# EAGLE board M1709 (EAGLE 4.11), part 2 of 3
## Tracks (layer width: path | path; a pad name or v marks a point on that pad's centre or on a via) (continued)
GND  (via drill 0.61) (continued)
  Top 0.381: U$2.AT2 212.72,13.97 212.72,24.77 BUS18.1 | U$2.AN2 225.43,13.97 225.43,24.77 BUS20.1 | U$2.AF1 244.47,13.97 244.47,24.77 BUS22.1 | U$2.AC1 254,13.97 v254,15.24 254,21.59 BUS23.1 | C4.2 157.48,80.65 157.48,75.57 159.38,73.66 v159.38,64.77 159.38,63.5 161.93,60.96 161.93,56.52 E3.1 | BUS7.1 224.79,32.39 224.16,33.02 224.16,41.91 C39.- | v90.17,66.04 90.17,79.38 88.9,80.65 R8.1 | 36.2,51.44 37.47,52.71 v37.47,59.69 37.47,61.6 | 37.47,61.6 36.2,62.87 E13.8 | 36.2,70.49 37.47,69.22 37.47,61.6 | BUS89.1 21.59,31.12 21.59,26.04 BUS97.1 22.23,24.77 v22.23,15.24 22.23,13.97 U$2.DN2 | U$2.DT2 9.53,13.97 9.53,24.77 BUS96.1 | E14.8 8.89,66.04 v5.71,62.87 3.81,60.96 3.81,37.47 8.89,32.39 BUS85.1 | U$2.CC1 120.65,13.97 v120.65,15.24 120.65,21.59 BUS81.1 | U$2.BT2 142.88,13.97 142.88,24.77 BUS41.1 | U$2.BN2 155.57,13.97 155.57,24.77 BUS42.1 | U$2.BF1 174.62,13.97 174.62,24.77 BUS47.1 | U$2.BC1 184.15,13.97 v184.15,15.24 184.15,21.59 BUS50.1 | C12.2 48.26,40.01 48.26,35.56 50.8,33.02 50.8,29.21 BUS95.1 | U$2.DF1 41.27,13.97 41.27,24.77 BUS99.1 40.64,26.04 40.64,31.12 BUS94.1 | U$2.DC1 50.8,13.97 50.8,21.59 BUS102.1 | U$2.CT2 79.38,13.97 79.38,24.77 BUS68.1 | U$2.CF1 111.12,13.97 v111.12,15.24 111.12,24.77 BUS78.1 | U$2.CN2 92.08,13.97 v92.08,15.24 92.08,24.77 BUS72.1 | E7.7 111.12,40.01 111.12,32.39 BUS64.1 | C3.2 157.48,55.25 155.57,53.34 155.57,32.39 BUS31.1 | E12.5 34.92,48.9 34.92,50.17 E12.4
  Bottom 0.381: C2.2 200.03,66.04 198.75,64.77 190.5,64.77 189.23,66.04 E2.7 186.69,66.04 185.42,64.77 v159.38,64.77 147.96,64.77 | C8.2 107.31,66.04 110.49,66.04 E8.7 113.03,66.04 114.3,64.77 139.7,64.77 | 139.7,64.77 138.43,66.04 E6.7 | 147.96,64.77 139.7,64.77 | 147.96,64.77 149.22,66.04 C6.2 | 253.37,14.61 254,13.97 U$2.AC2 | 253.37,14.61 252.73,15.24 247.65,15.24 246.38,13.97 U$2.AF2 244.47,13.97 241.94,16.51 229.87,16.51 227.33,13.97 U$2.AN2 225.43,13.97 224.16,15.24 215.9,15.24 214.63,13.97 U$2.AT2 | BUS22.1 243.84,26.04 243.84,31.12 BUS13.1 | 253.37,24.77 253.37,27.94 BUS16.1 | 253.37,24.77 253.37,22.86 BUS23.1 | 253.37,24.77 245.11,24.77 BUS22.1 | BUS18.1 213.36,24.77 214.63,23.5 223.52,23.5 224.79,24.77 BUS20.1 | BUS3.1 213.36,32.39 214.63,33.66 223.52,33.66 224.79,32.39 BUS7.1 224.79,31.12 224.79,26.04 BUS20.1 | BUS22.1 243.84,24.77 226.06,24.77 BUS20.1 | v254,15.24 253.37,14.61 | C15.- 234.95,42.55 224.79,42.55 C39.- 222.25,43.82 214,52.07 186.06,52.07 182.88,55.25 C1.2 | E4.1 161.29,81.28 158.12,81.28 C4.2 | C3.2 158.12,55.88 161.29,55.88 E3.1 163.83,55.88 165.1,57.15 180.97,57.15 182.25,55.88 C1.2 | E1.1 186.69,55.88 183.51,55.88 C1.2 | 59.69,174.63 C38.- 62.23,174.63 64.14,172.72 187.32,172.72 189.23,174.63 C37.- | U$2.DC2 50.8,13.97 49.53,15.24 44.45,15.24 43.18,13.97 U$2.DF2 41.27,13.97 40.01,15.24 v22.23,15.24 20.95,15.24 | 20.95,15.24 12.7,15.24 11.43,13.97 U$2.DT2 | 20.95,15.24 22.23,13.97 U$2.DN2 | C10.2 56.52,55.88 59.69,55.88 E10.1 60.33,56.52 60.33,65.41 E11.7 | R6.1 87,81.28 88.27,81.28 R8.1 | E11.7 59.69,66.04 56.52,66.04 C11.2 55.24,66.04 51.44,66.04 48.9,63.5 C13.2 47.62,63.5 45.09,60.96 38.73,60.96 v37.47,59.69
  Bottom 0.381: v90.17,66.04 88.9,64.77 63.5,64.77 62.23,66.04 E11.7 | 20.95,67.31 12.7,67.31 11.43,66.04 E14.8 | 20.95,67.31 22.23,66.04 C14.2 | 20.95,67.31 37.47,67.31 37.47,65.41 36.2,64.14 E13.8 | BUS85.1 8.89,31.12 8.89,26.04 BUS96.1 10.16,24.77 21.59,24.77 BUS97.1 | BUS89.1 22.86,31.12 23.5,30.48 27.3,30.48 27.94,29.85 30.48,29.85 31.11,30.48 33.66,30.48 34.29,29.85 39.37,29.85 40.64,31.12 BUS94.1 | 183.51,14.61 184.15,13.97 U$2.BC2 | 183.51,14.61 181.61,16.51 176.53,16.51 176.53,13.97 U$2.BF2 174.62,13.97 172.09,16.51 160.02,16.51 157.48,13.97 U$2.BN2 155.57,13.97 154.31,15.24 146.05,15.24 144.78,13.97 U$2.BT2 | 120.02,14.61 120.65,13.97 U$2.CC2 | 120.02,14.61 118.11,16.51 113.03,16.51 113.03,13.97 U$2.CF2 111.12,13.97 v111.12,15.24 | 183.51,23.5 183.51,27.94 BUS40.1 | 183.51,23.5 183.51,22.86 BUS50.1 | 183.51,23.5 180.34,23.5 179.71,24.13 175.9,24.13 175.26,24.77 BUS47.1 173.99,26.04 173.99,31.12 BUS37.1 173.99,32.39 172.72,33.66 158.12,33.66 156.84,32.39 156.21,32.39 BUS31.1 154.94,31.12 154.94,26.04 BUS42.1 154.94,25.4 143.51,25.4 BUS41.1 142.24,24.77 133.35,24.77 | 133.35,24.77 123.19,24.77 121.28,22.86 BUS81.1 | 133.35,24.77 139.06,30.48 141.6,30.48 142.24,31.12 BUS27.1 | v120.65,15.24 120.02,14.61 | v184.15,15.24 183.51,14.61 | C9.2 81.92,40.64 85.09,40.64 E9.8 87.63,40.64 88.9,39.37 104.78,39.37 106.05,40.64 C7.2 107.31,40.64 110.49,40.64 E7.7 113.03,40.64 113.67,40.64 116.2,38.1 128.91,38.1 131.44,40.64 C5.2 132.72,40.64 135.25,40.64 E5.8 | E12.8 36.83,40.64 38.1,41.91 46.35,41.91 47.62,40.64 C12.2 | BUS95.1 51.44,29.21 52.07,29.85 64.77,29.85 67.31,32.39 C40.- 69.85,33.66 77.47,33.66 78.74,32.39 BUS54.1
  Bottom 0.381: 91.44,14.61 92.08,13.97 U$2.CN2 | 91.44,14.61 89.53,16.51 81.28,16.51 81.28,13.97 U$2.CT2 | BUS64.1 111.76,31.75 117.47,31.75 120.02,29.21 BUS67.1 120.02,27.94 117.47,27.94 114.94,25.4 111.76,25.4 BUS78.1 110.49,26.04 109.86,26.67 106.05,26.67 105.41,27.31 102.87,27.31 102.23,26.67 99.69,26.67 99.06,27.31 96.52,27.31 95.25,26.04 92.71,26.04 BUS72.1 91.44,24.77 90.81,24.13 87,24.13 86.36,23.5 83.82,23.5 82.55,24.77 80.01,24.77 BUS68.1 | BUS99.1 41.27,25.4 45.09,25.4 46.99,23.5 49.53,23.5 50.16,22.86 BUS102.1 51.44,22.86 52.07,23.5 55.88,23.5 57.15,24.77 78.74,24.77 BUS68.1 | BUS68.1 78.74,26.04 78.74,31.12 BUS54.1 | BUS58.1 91.44,31.12 90.81,30.48 87,30.48 86.36,29.85 83.82,29.85 82.55,31.12 80.01,31.12 BUS54.1 | v92.08,15.24 91.44,14.61 | 12.06,128.27 12.06,98.43 4.45,98.43 3.17,97.16 3.17,62.87 v5.71,62.87 | E13.5 34.92,71.76 34.92,73.03 E13.4
  pour Top (isolate 0.406): 0,19.05 265.43,19.05 265.43,214.63 0,214.63
INITIALIZE  (via drill 0.61)
  Top 0.381: v89.53,55.88 89.53,40.01 90.81,38.74 90.81,33.66 v90.17,33.02 | U$2.CR1 87,13.97 87,24.13 87.63,24.77 87.63,27.31 86.36,28.58 86.36,31.12 BUS56.1
  Bottom 0.381: v89.53,55.88 92.71,55.88 E9.15 | v90.17,33.02 89.53,32.39 86.36,32.39 BUS56.1
INT_RQST\  (via drill 0.61)
  Top 0.381: v113.67,38.74 v113.67,46.99 | v89.53,38.1 89.53,34.29 88.9,33.66 88.9,29.21 BUS57.1 89.53,27.94 89.53,25.4 90.81,24.13 90.81,13.97 U$2.CP1
  Bottom 0.381: v113.67,46.99 116.84,46.99 118.11,45.72 E7.10 | v113.67,38.74 113.03,38.1 v89.53,38.1
INT_STROBE  (via drill 0.61)
  Top 0.381: v180.97,15.24 180.97,24.77 BUS49.1
  Bottom 0.381: v180.97,15.24 180.97,13.97 U$2.BD2
INTERNAL_IO\  (via drill 0.61)
  Top 0.381: v100.33,55.88 99.06,54.61 99.06,32.39 BUS60.1 99.06,31.12 99.06,28.58 100.33,27.31 100.33,24.77 99.69,24.13 99.69,13.97 U$2.CL1
  Bottom 0.381: v100.33,55.88 110.49,55.88 E7.1
IO_PAUSE\  (via drill 0.61)
  Top 0.381: v123.19,39.37 126.36,36.2 126.36,30.48 | 126.36,30.48 126.36,29.21 BUS66.1 | 126.36,30.48 118.75,22.86 118.75,13.97 U$2.CD1
  Bottom 0.381: v123.19,39.37 120.65,41.91 118.11,41.91 116.84,43.18 114.3,43.18 113.03,44.45 110.49,44.45 109.22,45.72 95.25,45.72 E9.11
LINK\  (via drill 0.61)
  Top 0.381: v207.01,19.05 207.01,24.77 BUS17.1
  Bottom 0.381: v207.01,19.05 207.01,13.97 U$2.AV2
LINK_DATA\  (via drill 0.61)
  Top 0.381: v85.72,15.24 85.72,24.77 BUS70.1
  Bottom 0.381: v85.72,15.24 85.72,13.97 U$2.CR2
LINK_LOAD\  (via drill 0.61)
  Top 0.381: v82.55,15.24 82.55,21.59 BUS69.1
  Bottom 0.381: v82.55,15.24 82.55,13.97 U$2.CS2
LOAD_CONT\  (via drill 0.61)
  Top 0.381: v171.45,15.24 171.45,21.59 BUS46.1
  Bottom 0.381: v171.45,15.24 171.45,13.97 U$2.BH2
MA00\
  Top 0.381: BUS15.1 250.82,31.12 250.82,13.97 U$2.AD1
MA01\
  Top 0.381: BUS14.1 247.65,27.94 247.65,13.97 U$2.AE1
MA02\
  Top 0.381: BUS12.1 241.3,27.94 241.3,13.97 U$2.AH1
MA03\
  Top 0.381: BUS11.1 238.12,31.12 238.12,13.97 U$2.AJ1
MA04\
  Top 0.381: BUS39.1 181.61,31.12 182.25,30.48 182.25,26.67 182.88,26.04 182.88,23.5 182.25,22.86 182.25,13.97 U$2.BD1
MA05\
  Top 0.381: BUS38.1 178.44,27.94 179.07,27.31 179.07,23.5 179.71,22.86 179.71,13.97 U$2.BE1
MA06\
  Top 0.381: BUS36.1 172.09,27.94 172.72,27.31 172.72,23.5 173.35,22.86 173.35,13.97 U$2.BH1
MA07
  Top 0.381: BUS35.1 168.91,31.12 169.54,30.48 169.54,26.67 170.18,26.04 170.18,23.5 169.54,22.86 169.54,13.97 U$2.BJ1
MA08\
  Top 0.381: BUS101.1 47.62,24.77 47.62,13.97 U$2.DD1
MA09\
  Top 0.381: BUS100.1 44.45,21.59 44.45,13.97 U$2.DE1
MA10\
  Top 0.381: BUS98.1 35.56,24.77 38.1,22.23 38.1,13.97 U$2.DH1
MA11\
  Top 0.381: BUS93.1 34.29,31.12 33.66,30.48 33.66,26.67 33.02,26.04 33.02,15.88 34.92,13.97 U$2.DJ1
MD00\
  Top 0.381: BUS10.1 235.59,27.94 236.85,26.67 236.85,13.97 U$2.AK1
MD01\
  Top 0.381: BUS9.1 231.78,31.12 231.78,13.97 U$2.AL1
MD02\
  Top 0.381: BUS8.1 228.6,27.94 228.6,13.97 U$2.AM1
MD03\  (via drill 0.61)
  Top 0.381: BUS6.1 221.62,27.94 221.62,23.5 v220.34,22.23 220.34,15.88 222.25,13.97 U$2.AP1
  Bottom 0.381: v220.34,22.23 202.56,22.23 200.66,20.32 188.59,20.32 188.59,26.67 177.16,38.1 139.06,38.1 139.06,45.72 137.16,47.63 E5.5
MD04\  (via drill 0.61)
  Top 0.381: v157.48,53.34 161.29,49.53 164.47,49.53 164.47,29.21 BUS34.1 165.74,27.94 165.74,25.4 167,24.13 167,13.97 U$2.BK1
  Bottom 0.381: v157.48,53.34 156.84,53.34 155.57,54.61 142.88,54.61 141.6,53.34 137.79,53.34 E5.3
MD05\  (via drill 0.61)
  Top 0.381: v140.34,48.26 140.34,54.61 137.16,57.79 E5.1 | v158.12,39.37 161.29,36.2 161.29,32.39 BUS33.1 162.56,31.12 162.56,28.58 163.83,27.31 163.83,24.77 163.19,24.13 163.19,13.97 U$2.BL1
  Bottom 0.381: v140.34,48.26 140.34,41.91 155.57,41.91 v158.12,39.37
MD06\  (via drill 0.61)
  Top 0.381: v88.27,38.1 88.27,56.52 87,57.79 E9.1 | v158.12,36.83 158.12,29.21 BUS32.1 158.75,27.94 158.75,13.97 U$2.BM1
  Bottom 0.381: v88.27,38.1 88.27,36.83 v158.12,36.83
MD07\  (via drill 0.61)
  Top 0.381: v138.43,54.61 139.06,53.98 139.06,46.99 139.7,46.36 139.7,32.39 137.79,30.48 v137.79,27.31 | U$2.BP1 152.4,13.97 152.4,27.94 BUS30.1
  Bottom 0.381: v138.43,54.61 88.9,54.61 87.63,53.34 E9.3 | v137.79,27.31 138.43,26.67 141.6,26.67 145.41,30.48 147.96,30.48 149.22,29.21 151.76,29.21 BUS30.1
MD08\  (via drill 0.61)
  Top 0.381: v36.2,35.56 32.38,31.75 32.38,29.21 BUS92.1 31.75,27.94 31.75,13.97 U$2.DK1
  Bottom 0.381: v36.2,35.56 38.1,35.56 39.37,36.83 60.96,36.83 66.04,41.91 69.85,41.91 72.39,44.45 88.27,44.45 88.27,46.36 87,47.63 E9.5
MD09\  (via drill 0.61)
  Top 0.381: v19.68,74.93 19.68,53.34 19.05,52.71 19.05,39.37 v25.4,33.02 | U$2.DL1 28.57,13.97 28.57,31.12 BUS91.1
  Bottom 0.381: v19.68,74.93 15.24,74.93 11.43,78.74 E14.3 | v25.4,33.02 26.04,32.39 27.94,32.39 BUS91.1
MD10\  (via drill 0.61)
  Top 0.381: v26.67,72.39 26.67,29.85 26.04,29.21 BUS90.1 25.4,27.94 25.4,13.97 U$2.DM1
  Bottom 0.381: v26.67,72.39 21.59,77.47 15.24,77.47 11.43,81.28 E14.2
MD11\  (via drill 0.61)
  Top 0.381: v13.97,33.02 13.97,52.71 13.34,53.34 13.34,80.65 10.79,83.19 E14.1 | U$2.DP1 19.05,13.97 19.05,27.31 BUS88.1
  Bottom 0.381: v13.97,33.02 13.97,29.85 17.14,29.85 18.41,28.58 BUS88.1
MD_DIR\  (via drill 0.61)
  Top 0.381: v234.95,15.24 234.95,21.59 BUS21.1
  Bottom 0.381: v234.95,15.24 234.95,13.97 U$2.AK2
MS_DISABLE\
  Top 0.381: BUS52.1 73.66,31.12 73.66,13.97 U$2.CV1
N$1
  Bottom 0.381: J1D.1 38.73,198.76 45.09,198.76 J1D1.1 | J1D.1 38.1,198.76 | J1.D 27.94,188.6 27.94,189.23 29.84,189.23 32.38,191.77 32.38,198.76 37.47,198.76 J1D.1
N$2
  Bottom 0.381: J1F1.1 45.09,194.95 38.73,194.95 J1F.1 37.47,194.95 36.83,194.95 33.66,194.95 33.66,190.5 29.84,186.69 27.94,186.69 27.94,186.06 J1.F
N$3
  Bottom 0.381: J1J1.1 45.09,191.14 38.73,191.14 J1J.1 37.47,191.14 36.83,191.14 34.92,191.14 34.92,189.23 29.84,184.15 27.94,184.15 27.94,183.52 J1.J
N$4
  Bottom 0.381: J1L1.1 45.09,187.33 38.73,187.33 J1L.1 37.47,187.33 35.56,187.33 29.84,181.61 27.94,181.61 27.94,180.98 J1.L
N$5
  Bottom 0.381: J1N1.1 45.09,183.52 38.73,183.52 J1N.1 37.47,183.52 35.56,183.52 30.48,178.44 28.57,178.44 28.57,177.8 J1.N
N$6
  Bottom 0.381: J1R1.1 45.09,179.71 38.73,179.71 J1R.1 37.47,179.71 35.56,179.71 31.75,175.9 28.57,175.9 28.57,175.26 J1.R
N$7
  Bottom 0.381: J1T1.1 45.09,175.9 38.73,175.9 J1T.1 37.47,175.9 35.56,175.9 33.02,173.36 28.57,173.36 28.57,172.72 J1.T
N$8
  Bottom 0.381: 37.47,172.09 J1V.1 | J1V1.1 45.09,172.09 38.73,172.09 J1V.1 | 37.47,172.09 35.56,172.09 34.29,170.82 28.57,170.82 28.57,170.18 J1.V | 37.47,172.09 J1V.1
N$9
  Bottom 0.381: 37.47,168.28 J1X.1 | J1X1.1 45.09,168.28 38.73,168.28 J1X.1 | 37.47,168.28 28.57,168.28 28.57,167.64 J1.X | 37.47,168.28 J1X.1
N$10
  Bottom 0.381: 37.47,165.1 J1Z.1 | J1Z1.1 45.09,164.47 38.73,164.47 J1Z.1 | 37.47,165.1 28.57,165.1 J1.Z | 37.47,165.1 J1Z.1
N$11
  Bottom 0.381: 37.47,161.93 J1BB.1 | J1BB1.1 45.09,160.66 38.73,160.66 J1BB.1 | 37.47,161.93 27.94,161.93 J1.BB | 37.47,161.93 J1BB.1
N$12
  Bottom 0.381: 37.47,158.12 J1DD.1 | J1DD1.1 45.09,156.85 38.73,156.85 J1DD.1 | 37.47,158.12 35.56,158.12 34.29,159.39 27.94,159.39 J1.DD | 37.47,158.12 J1DD.1
N$13
  Bottom 0.381: J1FF1.1 45.09,153.04 38.73,153.04 J1FF.1 37.47,154.31 35.56,154.31 33.02,156.85 27.94,156.85 J1.FF
N$14
  Bottom 0.381: J1JJ1.1 45.09,149.23 38.73,149.23 J1JJ.1 37.47,150.5 35.56,150.5 31.75,154.31 27.94,154.31 J1.JJ
N$15
  Bottom 0.381: J1LL1.1 45.09,145.42 38.73,145.42 J1LL.1 37.47,146.69 35.56,146.69 30.48,151.77 27.94,151.77 J1.LL
N$16
  Bottom 0.381: J1NN1.1 45.09,141.61 38.73,141.61 J1NN.1 37.47,142.88 35.56,142.88 29.84,148.59 27.94,148.59 27.94,149.23 J1.NN
N$17
  Bottom 0.381: 36.83,139.07 37.47,139.07 J1RR.1 | J1RR1.1 45.09,137.8 38.73,137.8 J1RR.1 | J1.RR 27.94,146.69 27.94,146.05 29.84,146.05 34.92,140.97 34.92,137.8 37.47,137.8 J1RR.1
N$18
  Bottom 0.381: 36.83,135.26 37.47,135.26 J1TT.1 | J1TT1.1 45.09,133.99 38.73,133.99 J1TT.1 | J1.TT 27.94,144.15 29.84,144.15 33.66,140.34 33.66,133.99 37.47,133.99 J1TT.1
N$19
  Top 0.381: FA1.1 137.16,191.14 137.16,200.66 F.A1
N$20
  Top 0.381: FB1.1 139.7,194.31 139.7,200.66 F.B1
N$21
  Top 0.381: FC1.1 142.88,191.14 142.88,200.66 F.C1
N$22
  Top 0.381: FD1.1 146.05,194.31 146.05,200.66 F.D1
N$23
  Top 0.381: FE1.1 149.22,191.14 149.22,200.66 F.E1
N$24
  Top 0.381: FF1.1 152.4,194.31 152.4,200.66 F.F1
N$25
  Top 0.381: FH1.1 155.57,191.14 155.57,200.66 F.H1
N$26
  Top 0.381: FJ1.1 158.75,194.31 158.75,200.66 F.J1
N$27
  Top 0.381: FK1.1 161.93,191.14 161.93,200.66 F.K1
N$28
  Top 0.381: FL1.1 165.1,194.31 165.1,200.66 F.L1
N$29
  Top 0.381: FM1.1 168.28,191.14 168.28,200.66 F.M1
N$30
  Top 0.381: FN1.1 171.45,194.31 171.45,200.66 F.N1
N$31
  Top 0.381: FP1.1 174.62,191.14 174.62,200.66 F.P1
N$32
  Top 0.381: FR1.1 177.8,194.31 177.8,200.66 F.R1
N$33
  Top 0.381: FS1.1 180.97,191.14 180.97,200.66 F.S1
N$34
  Top 0.381: FT1.1 184.15,194.31 184.15,200.66 F.T1
N$35
  Top 0.381: FU1.1 187.32,191.14 187.32,200.66 F.U1
N$36
  Top 0.381: FV1.1 190.5,194.31 190.5,200.66 F.V1
N$37
  Bottom 0.381: FA2.1 135.89,184.79 135.89,188.6 134.62,189.87 134.62,197.49 135.89,197.49 137.16,198.76 137.16,200.66 F.A2
N$38
  Bottom 0.381: FB2.1 139.06,187.96 139.06,191.77 137.79,193.04 137.79,198.12 140.34,200.66 F.B2
N$39
  Bottom 0.381: FC2.1 142.24,184.79 142.24,188.6 140.97,189.87 140.97,192.41 142.88,194.31 142.88,200.66 F.C2
N$40
  Bottom 0.381: FD2.1 145.41,187.96 145.41,191.77 144.15,193.04 144.15,200.03 145.41,200.03 146.05,200.66 F.D2
N$41
  Bottom 0.381: FE2.1 148.59,184.79 148.59,188.6 147.32,189.87 147.32,192.41 149.22,194.31 149.22,200.66 F.E2
N$42
  Bottom 0.381: FF2.1 151.76,187.96 151.76,191.77 150.5,193.04 150.5,200.03 151.76,200.03 152.4,200.66 F.F2
N$43
  Bottom 0.381: FH2.1 154.94,184.79 154.94,188.6 153.67,189.87 153.67,192.41 155.57,194.31 155.57,200.66 F.H2
N$44
  Bottom 0.381: FJ2.1 158.12,187.96 158.12,191.77 156.84,193.04 156.84,200.03 158.12,200.03 158.75,200.66 F.J2
N$45
  Bottom 0.381: FK2.1 161.29,184.79 161.29,188.6 160.02,189.87 160.02,192.41 161.93,194.31 161.93,200.66 F.K2
N$46
  Bottom 0.381: FL2.1 164.47,187.96 164.47,191.77 163.19,193.04 163.19,200.03 164.47,200.03 165.1,200.66 F.L2
N$47
  Bottom 0.381: FM2.1 167.64,184.79 167.64,188.6 166.37,189.87 166.37,192.41 168.28,194.31 168.28,200.66 F.M2
N$48
  Bottom 0.381: FN2.1 170.81,187.96 170.81,191.77 169.54,193.04 169.54,200.03 170.81,200.03 171.45,200.66 F.N2
N$49
  Bottom 0.381: FP2.1 173.99,184.79 173.99,188.6 172.72,189.87 172.72,192.41 174.62,194.31 174.62,200.66 F.P2
N$50
  Bottom 0.381: FR2.1 177.16,187.96 177.16,191.77 175.9,193.04 175.9,200.03 177.16,200.03 177.8,200.66 F.R2
N$51
  Bottom 0.381: FS2.1 180.34,184.79 180.34,188.6 179.07,189.87 179.07,192.41 180.97,194.31 180.97,200.66 F.S2
N$52
  Bottom 0.381: FT2.1 183.51,187.96 183.51,191.77 182.25,193.04 182.25,200.03 183.51,200.03 184.15,200.66 F.T2
N$53
  Bottom 0.381: FU2.1 186.69,184.79 186.69,188.6 185.42,189.87 185.42,192.41 187.32,194.31 187.32,200.66 F.U2
N$54
  Bottom 0.381: FV2.1 189.87,187.96 189.87,191.77 188.59,193.04 188.59,200.03 189.87,200.03 190.5,200.66 F.V2
N$55
  Bottom 0.381: HA2.1 72.39,184.79 72.39,188.6 71.12,189.87 71.12,197.49 72.39,197.49 73.66,198.76 73.66,200.66 H.A2
N$56
  Bottom 0.381: HB2.1 75.56,187.96 75.56,191.77 74.3,193.04 74.3,198.12 76.83,200.66 H.B2
N$57
  Bottom 0.381: HC2.1 78.74,184.79 78.74,188.6 77.47,189.87 77.47,192.41 79.38,194.31 79.38,200.66 H.C2
N$58
  Bottom 0.381: HD2.1 81.92,187.96 81.92,191.77 80.64,193.04 80.64,200.03 81.92,200.03 82.55,200.66 H.D2
N$59
  Bottom 0.381: HE2.1 85.09,184.79 85.09,188.6 83.82,189.87 83.82,192.41 85.72,194.31 85.72,200.66 H.E2
N$60
  Bottom 0.381: HF2.1 88.27,187.96 88.27,191.77 87,193.04 87,200.03 88.27,200.03 88.9,200.66 H.F2
N$61
  Bottom 0.381: HH2.1 91.44,184.79 91.44,188.6 90.17,189.87 90.17,192.41 92.08,194.31 92.08,200.66 H.H2
N$62
  Bottom 0.381: HJ2.1 94.61,187.96 94.61,191.77 93.34,193.04 93.34,200.03 94.61,200.03 95.25,200.66 H.J2
N$63
  Bottom 0.381: HK2.1 97.79,184.79 97.79,188.6 96.52,189.87 96.52,192.41 98.42,194.31 98.42,200.66 H.K2
N$64
  Bottom 0.381: HL2.1 100.97,187.96 100.97,191.77 99.69,193.04 99.69,200.03 100.97,200.03 101.6,200.66 H.L2
N$65
  Bottom 0.381: HM2.1 104.14,184.79 104.14,188.6 102.87,189.87 102.87,192.41 104.78,194.31 104.78,200.66 H.M2
N$66
  Bottom 0.381: HN2.1 107.31,187.96 107.31,191.77 106.05,193.04 106.05,200.03 107.31,200.03 107.95,200.66 H.N2
N$67
  Bottom 0.381: HP2.1 110.49,184.79 110.49,188.6 109.22,189.87 109.22,192.41 111.12,194.31 111.12,200.66 H.P2
N$68
  Bottom 0.381: HR2.1 113.67,187.96 113.67,191.77 112.39,193.04 112.39,200.03 113.67,200.03 114.3,200.66 H.R2
N$69
  Bottom 0.381: HS2.1 116.84,184.79 116.84,188.6 115.57,189.87 115.57,192.41 117.47,194.31 117.47,200.66 H.S2
N$70
  Bottom 0.381: HT2.1 120.02,187.96 120.02,191.77 118.75,193.04 118.75,200.03 120.02,200.03 120.65,200.66 H.T2
N$71
  Bottom 0.381: HU2.1 123.19,184.79 123.19,188.6 121.92,189.87 121.92,192.41 123.83,194.31 123.83,200.66 H.U2
N$72
  Bottom 0.381: HV2.1 126.36,187.96 126.36,191.77 125.09,193.04 125.09,200.03 126.36,200.03 127,200.66 H.V2
N$73
  Top 0.381: HA1.1 73.66,191.14 73.66,200.66 H.A1
N$74
  Top 0.381: HB1.1 76.2,194.31 76.2,200.66 H.B1
N$75
  Top 0.381: HC1.1 79.38,191.14 79.38,200.66 H.C1
N$76
  Top 0.381: HD1.1 82.55,194.31 82.55,200.66 H.D1
N$77
  Top 0.381: HE1.1 85.72,191.14 85.72,200.66 H.E1
N$78
  Top 0.381: HF1.1 88.9,194.31 88.9,200.66 H.F1
N$79
  Top 0.381: HH1.1 92.08,191.14 92.08,200.66 H.H1
N$80
  Top 0.381: HJ1.1 95.25,194.31 95.25,200.66 H.J1
N$81
  Top 0.381: HK1.1 98.42,191.14 98.42,200.66 H.K1
N$82
  Top 0.381: HL1.1 101.6,194.31 101.6,200.66 H.L1
N$83
  Top 0.381: HM1.1 104.78,191.14 104.78,200.66 H.M1
N$84
  Top 0.381: HN1.1 107.95,194.31 107.95,200.66 H.N1
N$85
  Top 0.381: HP1.1 111.12,191.14 111.12,200.66 H.P1
N$86
  Top 0.381: HR1.1 114.3,194.31 114.3,200.66 H.R1
N$87
  Top 0.381: HS1.1 117.47,191.14 117.47,200.66 H.S1
N$88
  Top 0.381: HT1.1 120.65,194.31 120.65,200.66 H.T1
N$89
  Top 0.381: HU1.1 123.83,191.14 123.83,200.66 H.U1
N$90
  Top 0.381: HV1.1 127,194.31 127,200.66 H.V1
N$91
  Bottom 0.381: E17.1 241.3,116.84 240.03,116.84 SV1.1 237.49,116.84 234.31,116.84 E17-1.1
N$92
  Bottom 0.381: E17.2 241.3,114.3 240.03,114.3 SV1.2 237.49,114.3 234.95,114.3 234.31,113.67 E17-2.1
N$93
  Bottom 0.381: E17.3 241.3,111.76 240.03,111.76 SV1.3 237.49,111.76 235.59,111.76 234.31,110.49 E17-3.1
N$94
  Bottom 0.381: E17.4 241.3,109.22 240.03,109.22 SV1.4 237.49,109.22 236.22,109.22 234.31,107.32 E17-4.1
N$95
  Bottom 0.381: E17.5 241.3,106.68 240.03,106.68 SV1.5 237.49,106.68 236.85,106.68 234.31,104.14 E17-5.1
N$96
  Bottom 0.381: E17.6 241.3,104.14 240.03,104.14 SV1.6 237.49,104.14 234.31,100.97 E17-6.1
N$97
  Bottom 0.381: E17.7 241.3,101.6 240.03,101.6 SV1.7 238.12,100.97 237.49,100.97 234.31,97.79 E17-7.1
N$98
  Bottom 0.381: E17.8 241.3,99.06 240.03,99.06 SV1.8 237.49,99.06 233.68,95.25 E17-8.1
N$99
  Bottom 0.381: SV1.9 237.49,96.52 233.68,92.71 233.68,92.08 E17-9.1
N$100
  Bottom 0.381: C17.1 241.94,93.98 240.03,93.98 SV1.10 237.49,93.98 236.85,93.98 236.85,92.08 233.68,88.9 E17-10.1
N$101
  Bottom 0.381: C17.2 250.82,93.98 252.73,93.98 SV2.10 254.63,93.35 255.27,93.35 256.54,92.08 256.54,90.81 258.44,88.9 E17-15.1
N$102
  Bottom 0.381: SV2.9 255.27,96.52 257.18,94.62 257.18,92.71 257.81,92.71 258.44,92.08 E17-16.1
N$103
  Bottom 0.381: E17.9 251.46,99.06 252.73,99.06 SV2.8 254.63,98.43 255.27,98.43 258.44,95.25 E17-17.1
N$104
  Bottom 0.381: E17.10 251.46,101.6 252.73,101.6 SV2.7 255.27,101.6 258.44,98.43 E17-18.1
N$105
  Bottom 0.381: E17.11 251.46,104.14 252.73,104.14 SV2.6 254.63,103.51 255.27,103.51 257.81,100.97 E17-19.1
N$106
  Bottom 0.381: E17.12 251.46,106.68 252.73,106.68 SV2.5 255.27,106.68 257.81,104.14 E17-20.1
N$107
  Bottom 0.381: E17.13 251.46,109.22 252.73,109.22 SV2.4 255.27,109.22 255.91,109.22 257.81,107.32 E17-21.1
N$108
  Bottom 0.381: E17.14 251.46,111.76 252.73,111.76 SV2.3 255.27,111.76 256.54,111.76 257.81,110.49 E17-22.1
N$109
  Bottom 0.381: E17.15 251.46,114.3 252.73,114.3 SV2.2 255.27,114.3 257.18,114.3 257.81,113.67 E17-23.1
N$110
  Bottom 0.381: E17.16 251.46,116.84 252.73,116.84 SV2.1 255.27,116.84 257.81,116.84 E17-24.1
N$111
  Bottom 0.381: SV3.11 237.49,121.92 236.22,123.19 234.31,123.19 E18-11.1
N$112
  Bottom 0.381: SV3.12 237.49,119.38 236.85,120.02 234.31,120.02 E18-12.1
N$113
  Bottom 0.381: SV4.12 255.27,119.38 255.91,120.02 257.81,120.02 E18-13.1
N$114
  Bottom 0.381: SV4.11 255.27,121.92 256.54,123.19 257.81,123.19 E18-14.1
N$115
  Bottom 0.381: E18.1 241.3,147.32 240.03,147.32 SV3.1 238.12,147.96 236.85,147.96 236.85,149.23 236.22,149.86 236.22,151.77 233.68,154.31 E18-1.1
N$116
  Bottom 0.381: E18.2 241.3,144.78 240.03,144.78 SV3.2 238.12,145.42 237.49,145.42 235.59,147.32 235.59,149.23 233.68,151.13 E18-2.1
N$117
  Bottom 0.381: SV1.11 237.49,91.44 234.95,88.9 234.95,87.63 233.68,86.36 233.68,85.73 E17-11.1
N$118
  Bottom 0.381: SV1.12 237.49,88.9 234.95,86.36 234.95,82.55 233.68,82.55 E17-12.1
N$119
  Bottom 0.381: SV8.1 240.03,86.36 241.3,86.36 E16.1 243.21,85.73 244.47,85.73 244.47,80.65 243.84,80.01 236.85,80.01 236.22,79.38 234.95,79.38 234.31,78.74 E16-1.1
N$120
  Top 0.381: E16-2.1 233.68,76.2 236.22,78.74 236.22,82.55 237.49,83.82 SV8.2
  Bottom 0.381: E16.2 241.3,83.82 240.03,83.82 SV8.2
N$121
  Bottom 0.381: E16.3 241.3,81.28 240.03,81.28 SV8.3 237.49,81.28 236.85,81.28 236.22,80.65 232.41,80.65 232.41,74.3 233.68,73.03 E16-3.1
N$122
  Bottom 0.381: E16.4 241.3,78.74 240.03,78.74 SV8.4 238.12,78.11 234.95,78.11 234.95,71.12 233.68,69.85 E16-4.1
N$123
  Bottom 0.381: E16.5 241.3,76.2 240.03,76.2 SV8.5 237.49,76.2 236.22,76.2 236.22,70.49 236.85,69.85 244.47,69.85 244.47,67.95 243.21,66.68 234.95,66.68 234.31,66.04 E16-5.1
N$124
  Top 0.381: E16-6.1 233.68,63.5 236.22,66.04 236.22,72.39 237.49,73.66 SV8.6
  Bottom 0.381: E16.6 241.3,73.66 240.03,73.66 SV8.6
N$125
  Bottom 0.381: SV8.7 240.03,71.12 241.3,71.12 E16.7 243.84,71.12 245.75,71.12 245.75,67.95 243.21,65.41 240.03,65.41 234.31,59.69 E16-7.1
N$126
  Bottom 0.381: E16.8 241.3,68.58 240.03,68.58 SV8.8 238.12,67.95 232.41,67.95 232.41,58.42 233.68,57.15 E16-8.1
N$127
  Bottom 0.381: E16.9 251.46,68.58 252.73,68.58 SV7.8 254.63,67.95 254.63,60.96 258.44,57.15 E16-9.1
N$128
  Bottom 0.381: E16.10 251.46,71.12 252.73,71.12 SV7.7 255.27,71.12 259.71,71.12 259.71,65.41 259.08,64.77 257.18,64.77 257.18,61.6 258.44,60.33 E16-10.1
N$129
  Bottom 0.381: E16.11 251.46,73.66 252.73,73.66 SV7.6 255.27,73.66 260.99,73.66 260.99,64.77 259.08,62.87 E16-11.1
N$130
  Bottom 0.381: SV7.5 252.73,76.2 251.46,76.2 E16.12 248.92,76.2 248.28,76.2 248.28,70.49 248.92,69.85 255.91,69.85 255.91,69.22 258.44,66.68 E16-12.1
N$131
  Top 0.381: E16-13.1 258.44,69.85 255.91,72.39 248.28,72.39 248.28,76.84 249.56,78.11 E16.13
  Bottom 0.381: E16.13 251.46,78.74 252.73,78.74 SV7.4
N$132
  Top 0.381: E16-14.1 258.44,73.03 256.54,74.93 256.54,80.01 255.27,81.28 SV7.3
  Bottom 0.381: E16.14 251.46,81.28 252.73,81.28 SV7.3
N$133
  Bottom 0.381: SV7.2 252.73,83.82 251.46,83.82 E16.15 248.92,83.82 248.28,83.82 248.28,80.65 248.92,80.01 256.54,80.01 256.54,78.11 258.44,76.2 E16-15.1
N$134
  Bottom 0.381: E16.16 251.46,86.36 252.73,86.36 SV7.1 254.63,85.73 256.54,85.73 256.54,81.28 258.44,79.38 E16-16.1
N$135
  Top 0.381: SV2.12 255.27,88.9 257.18,87 257.18,83.82 258.44,82.55 E17-13.1
N$136
  Bottom 0.381: SV2.11 252.73,91.44 250.82,89.54 250.82,87.63 256.54,87.63 258.44,85.73 E17-14.1
N$137
  Bottom 0.381: E18.3 241.3,142.24 240.03,142.24 SV3.3 237.49,142.24 236.22,143.51 236.22,145.42 233.68,147.96 E18-3.1
N$138
  Bottom 0.381: E18.4 241.3,139.7 240.03,139.7 SV3.4 238.12,140.34 236.85,140.34 236.85,141.61 233.68,144.78 E18-4.1
N$139
  Bottom 0.381: E18.5 241.3,137.16 240.03,137.16 SV3.5 238.12,137.8 237.49,137.8 233.68,141.61 E18-5.1
N$140
  Bottom 0.381: E18.6 241.3,134.62 240.03,134.62 SV3.6 237.49,134.62 233.68,138.43 E18-6.1
N$141
  Bottom 0.381: E18.7 241.3,132.08 240.03,132.08 SV3.7 237.49,132.08 236.85,132.08 233.68,135.26 E18-7.1
N$142
  Bottom 0.381: E18.8 241.3,129.54 240.03,129.54 SV3.8 237.49,129.54 234.31,132.72 E18-8.1
N$143
  Bottom 0.381: SV3.9 237.49,127 234.95,129.54 234.31,129.54 E18-9.1
N$144
  Bottom 0.381: C18.1 241.94,124.46 240.03,124.46 SV3.10 237.49,124.46 236.22,124.46 234.31,126.37 E18-10.1
N$145
  Bottom 0.381: C18.2 250.82,124.46 252.73,124.46 SV4.10 255.27,124.46 255.91,124.46 257.81,126.37 E18-15.1
N$146
  Bottom 0.381: SV4.9 255.27,127 257.81,129.54 E18-16.1
N$147
  Bottom 0.381: E18.9 251.46,129.54 252.73,129.54 SV4.8 255.27,129.54 255.91,129.54 258.44,132.08 E18-17.1
N$148
  Bottom 0.381: E18.10 251.46,132.08 252.73,132.08 SV4.7 255.27,132.08 258.44,135.26 E18-18.1
N$149
  Bottom 0.381: E18.11 251.46,134.62 252.73,134.62 SV4.6 254.63,135.26 255.27,135.26 258.44,138.43 E18-19.1
N$150
  Bottom 0.381: E18.12 251.46,137.16 252.73,137.16 SV4.5 254.63,137.8 255.91,137.8 255.91,139.07 258.44,141.61 E18-20.1
N$151
  Bottom 0.381: E18.13 251.46,139.7 252.73,139.7 SV4.4 254.63,140.34 255.91,140.34 255.91,141.61 257.81,143.51 258.44,143.51 258.44,144.78 E18-21.1
N$152
  Bottom 0.381: E18.14 251.46,142.24 252.73,142.24 SV4.3 255.27,142.24 256.54,143.51 256.54,145.42 257.81,146.69 258.44,146.69 258.44,147.96 E18-22.1
N$153
  Bottom 0.381: E18.15 251.46,144.78 252.73,144.78 SV4.2 254.63,145.42 255.27,145.42 257.18,147.32 257.18,149.23 257.81,149.86 258.44,149.86 258.44,151.13 E18-23.1
N$154
  Bottom 0.381: E18.16 251.46,147.32 252.73,147.32 SV4.1 254.63,147.96 255.91,147.96 255.91,149.23 256.54,149.86 256.54,152.4 258.44,154.31 E18-24.1
N$155
  Top 0.381: SV5.11 237.49,152.4 234.95,154.94 234.95,159.39 233.68,160.66 E19-11.1
N$156
  Bottom 0.381: SV5.12 240.03,149.86 243.84,153.67 243.84,156.21 236.22,156.21 234.31,158.12 E19-12.1
N$157
  Top 0.381: SV6.12 255.27,149.86 257.18,151.77 257.18,155.58 258.44,156.85 258.44,157.48 E19-13.1
N$158
  Bottom 0.381: SV6.11 255.27,152.4 257.18,154.31 257.18,161.29 257.81,161.29 E19-14.1
N$159
  Top 0.381: E19-1.1 233.68,192.41 238.12,187.96 238.12,178.44 SV5.1
  Bottom 0.381: E19.1 241.3,177.8 240.03,177.8 SV5.1
N$160
  Bottom 0.381: SV5.2 240.03,175.26 241.3,175.26 E19.2 243.21,175.9 244.47,175.9 244.47,179.71 234.31,189.87 E19-2.1
N$161
  Bottom 0.381: E19.3 241.3,172.72 240.03,172.72 SV5.3 238.12,173.36 236.22,173.36 236.22,176.53 234.31,178.44 232.41,178.44 232.41,184.79 233.68,186.06 E19-3.1
N$162
  Bottom 0.381: SV5.4 240.03,170.18 241.3,170.18 E19.4 243.21,170.82 245.75,170.82 245.75,179.71 234.31,191.14 232.41,191.14 232.41,189.23 233.68,187.96 234.95,187.96 234.95,185.42 233.68,184.15 E19-4.1
N$163
  Top 0.381: E19-5.1 233.68,179.71 236.22,177.17 236.22,168.91 237.49,167.64 SV5.5
  Bottom 0.381: E19.5 241.3,167.64 240.03,167.64 SV5.5
N$164  (via drill 0.61)
  Top 0.381: v244.47,168.91 244.47,167.01 243.21,165.74 E19.6
  Bottom 0.381: E19.6 241.3,165.1 240.03,165.1 SV5.6 | v244.47,168.91 234.95,168.91 234.95,175.26 233.68,176.53 E19-6.1
N$165
  Top 0.381: E19-7.1 233.68,173.36 234.95,172.09 234.95,165.1 237.49,162.56 SV5.7
  Bottom 0.381: E19.7 241.3,162.56 240.03,162.56 SV5.7
N$166
  Bottom 0.381: E19.8 241.3,160.02 240.03,160.02 SV5.8 237.49,160.02 232.41,160.02 232.41,168.91 233.68,170.18 E19-8.1
N$167
  Bottom 0.381: SV5.9 240.03,157.48 241.3,158.75 243.84,158.75 244.47,159.39 244.47,166.37 235.59,166.37 234.31,167.64 E19-9.1
N$168
  Top 0.381: E19-10.1 233.68,163.83 236.22,161.29 236.22,156.21 237.49,154.94 SV5.10
  Bottom 0.381: C19.1 241.94,154.94 240.03,154.94 SV5.10
N$169
  Top 0.381: E19-15.1 258.44,163.83 257.81,163.2 257.81,162.56 257.18,161.93 257.18,156.85 255.27,154.94 SV6.10
  Bottom 0.381: C19.2 250.82,154.94 252.73,154.94 SV6.10
N$170
  Bottom 0.381: SV6.9 252.73,157.48 251.46,158.75 248.92,158.75 247.01,160.66 247.01,166.37 256.54,166.37 257.81,167.64 E19-16.1
N$171
  Top 0.381: E19-17.1 258.44,170.18 256.54,168.28 256.54,162.56 255.91,161.93 255.91,160.66 255.27,160.02 SV6.8
  Bottom 0.381: E19.9 251.46,160.02 252.73,160.02 SV6.8
N$172
  Bottom 0.381: E19.10 251.46,162.56 252.73,162.56 SV6.7 254.63,163.2 255.27,163.2 257.81,165.74 259.71,165.74 259.71,172.09 258.44,173.36 E19-18.1
N$173
  Bottom 0.381: SV6.6 252.73,165.1 251.46,165.1 E19.11 248.92,165.1 248.28,165.1 248.28,161.93 248.92,161.29 255.91,161.29 257.18,162.56 260.99,162.56 260.99,173.99 258.44,176.53 E19-19.1
N$174
  Top 0.381: E19-20.1 258.44,179.71 256.54,177.8 256.54,169.55 255.27,168.28 255.27,167.64 SV6.5
  Bottom 0.381: E19.12 251.46,167.64 252.73,167.64 SV6.5
N$175
  Top 0.381: E19-21.1 257.81,183.52 248.28,183.52 248.28,172.09 249.56,170.82 E19.13
  Bottom 0.381: E19.13 251.46,170.18 252.73,170.18 SV6.4
N$176
  Bottom 0.381: SV6.3 252.73,172.72 251.46,172.72 E19.14 249.56,173.36 248.28,173.36 248.28,178.44 248.92,179.07 250.19,179.07 257.81,186.69 E19-22.1
N$177
  Bottom 0.381: E19.15 251.46,175.26 252.73,175.26 SV6.2 254.63,175.9 255.27,175.9 257.81,178.44 260.99,178.44 260.99,192.41 259.08,194.31 257.18,194.31 257.18,191.77 258.44,190.5 E19-23.1
N$178
  Bottom 0.381: E19.16 251.46,177.8 252.73,177.8 SV6.1 254.63,178.44 257.81,181.61 259.71,181.61 259.71,191.14 258.44,192.41 E19-24.1
N$179
  Bottom 0.381: C16.1 240.66,53.34 234.31,53.34 C1-1.1
N$180
  Bottom 0.381: C16.2 249.56,53.34 257.81,53.34 C1-2.1
N$181
  Bottom 0.381: E21.1 212.72,160.66 208.91,164.47 E16-19.1
N$182
  Bottom 0.381: E21.2 212.09,157.48 208.91,160.66 E16-20.1
N$183
  Bottom 0.381: E21.3 212.09,154.94 210.19,156.85 208.91,156.85 E16-21.1
N$184
  Bottom 0.381: E21.4 212.09,152.4 211.46,153.04 208.91,153.04 E16-22.1
N$185
  Bottom 0.381: E21.5 212.09,149.86 208.91,149.86 E16-23.1
N$186
  Bottom 0.381: E21.6 212.09,147.32 211.46,146.69 208.91,146.69 E16-24.1
N$187
  Bottom 0.381: E21.7 212.09,144.78 210.19,142.88 208.91,142.88 E16-25.1
N$188
  Bottom 0.381: E21.8 212.09,142.24 208.91,139.07 E16-26.1
N$189
  Bottom 0.381: E21.9 222.25,142.24 225.43,139.07 E16-27.1
N$190
  Bottom 0.381: E21.10 222.25,144.78 224.16,142.88 225.43,142.88 E16-28.1
N$191
  Bottom 0.381: E21.11 222.25,147.32 222.88,146.69 225.43,146.69 E16-29.1
N$192
  Bottom 0.381: E21.12 222.25,149.86 225.43,149.86 E16-30.1
N$193
  Bottom 0.381: E21.13 222.25,152.4 222.88,153.04 225.43,153.04 E16-31.1
N$194
  Bottom 0.381: E21.14 222.25,154.94 224.16,156.85 225.43,156.85 E16-32.1
N$195
  Bottom 0.381: E21.15 222.25,157.48 225.43,160.66 E16-33.1
N$196
  Bottom 0.381: E21.16 221.62,160.66 225.43,164.47 E16-34.1
N$197
  Bottom 0.381: C21.1 212.72,134.62 208.91,134.62 E16-35.1
N$198
  Bottom 0.381: C21.2 221.62,134.62 225.43,134.62 E16-36.1
N$199
  Bottom 0.381: E20.1 212.72,122.56 208.91,126.37 E16-37.1
N$200
  Bottom 0.381: E20.2 212.09,119.38 208.91,122.56 E16-38.1
N$201
  Bottom 0.381: E20.3 212.09,116.84 210.19,118.75 208.91,118.75 E16-39.1
N$202
  Bottom 0.381: E20.4 212.09,114.3 211.46,114.94 208.91,114.94 E16-40.1
N$203
  Bottom 0.381: E20.5 212.09,111.76 208.91,111.76 E16-65.1
N$204
  Bottom 0.381: E20.6 212.09,109.22 211.46,108.59 208.91,108.59 E16-66.1
N$205
  Bottom 0.381: E20.7 212.09,106.68 210.19,104.78 208.91,104.78 E16-67.1
N$206
  Bottom 0.381: E20.8 212.09,104.14 208.91,100.97 E16-68.1
N$207
  Bottom 0.381: E20.9 222.25,104.14 225.43,100.97 E16-69.1
N$208
  Bottom 0.381: E20.10 222.25,106.68 224.16,104.78 225.43,104.78 E16-70.1
N$209
  Bottom 0.381: E20.11 222.25,109.22 222.88,108.59 225.43,108.59 E16-71.1
N$210
  Bottom 0.381: E20.12 222.25,111.76 225.43,111.76 E16-72.1
N$211
  Bottom 0.381: E20.13 222.25,114.3 222.88,114.94 225.43,114.94 E16-73.1
N$212
  Bottom 0.381: E20.14 222.25,116.84 224.16,118.75 225.43,118.75 E16-74.1
N$213
  Bottom 0.381: E20.15 222.25,119.38 225.43,122.56 E16-75.1
N$214
  Bottom 0.381: E20.16 221.62,122.56 225.43,126.37 E16-76.1
N$215
  Bottom 0.381: C20.1 212.72,96.52 208.91,96.52 E16-77.1
N$216
  Bottom 0.381: C20.2 221.62,96.52 225.43,96.52 E16-78.1
N$217
  Bottom 0.381: E24.1 187.32,160.66 183.51,164.47 E16-79.1
N$218
  Bottom 0.381: E24.2 186.69,157.48 183.51,160.66 E16-80.1
N$219
  Bottom 0.381: E24.3 186.69,154.94 184.78,156.85 183.51,156.85 E16-81.1
N$220
  Bottom 0.381: E24.4 186.69,152.4 186.06,153.04 183.51,153.04 E16-82.1
N$221
  Bottom 0.381: E24.5 186.69,149.86 183.51,149.86 E16-83.1
N$222
  Bottom 0.381: E24.6 186.69,147.32 186.06,146.69 183.51,146.69 E16-84.1
N$223
  Bottom 0.381: E24.7 186.69,144.78 184.78,142.88 183.51,142.88 E16-85.1
N$224
  Bottom 0.381: E24.8 186.69,142.24 183.51,139.07 E16-86.1
N$225
  Bottom 0.381: E24.9 196.85,142.24 200.03,139.07 E16-87.1
N$226
  Bottom 0.381: E24.10 196.85,144.78 198.75,142.88 200.03,142.88 E16-88.1
N$227
  Bottom 0.381: E24.11 196.85,147.32 197.49,146.69 200.03,146.69 E16-89.1
N$228
  Bottom 0.381: E24.12 196.85,149.86 200.03,149.86 E16-90.1
N$229
  Bottom 0.381: E24.13 196.85,152.4 197.49,153.04 200.03,153.04 E16-91.1
N$230
  Bottom 0.381: E24.14 196.85,154.94 198.75,156.85 200.03,156.85 E16-92.1
N$231
  Bottom 0.381: E24.15 196.85,157.48 200.03,160.66 E16-93.1
N$232
  Bottom 0.381: E24.16 196.22,160.66 200.03,164.47 E16-94.1
N$233
  Bottom 0.381: C24.1 187.32,134.62 183.51,134.62 E16-95.1
N$234
  Bottom 0.381: C24.2 196.22,134.62 200.03,134.62 E16-96.1
N$235
  Bottom 0.381: E23.1 187.32,122.56 183.51,126.37 E16-97.1
N$236
  Bottom 0.381: E23.2 186.69,119.38 183.51,122.56 E16-98.1
N$237
  Bottom 0.381: E23.3 186.69,116.84 184.78,118.75 183.51,118.75 E16-99.1
N$238
  Bottom 0.381: E23.4 186.69,114.3 186.06,114.94 183.51,114.94 E16-100.1
N$239
  Bottom 0.381: E23.5 186.69,111.76 183.51,111.76 E16-101.1
N$240
  Bottom 0.381: E23.6 186.69,109.22 186.06,108.59 183.51,108.59 E16-102.1
N$241
  Bottom 0.381: E23.7 186.69,106.68 184.78,104.78 183.51,104.78 E16-103.1
N$242
  Bottom 0.381: E23.8 186.69,104.14 183.51,100.97 E16-104.1
N$243
  Bottom 0.381: E23.9 196.85,104.14 200.03,100.97 E16-105.1
N$244
  Bottom 0.381: E23.10 196.85,106.68 198.75,104.78 200.03,104.78 E16-106.1
N$245
  Bottom 0.381: E23.11 196.85,109.22 197.49,108.59 200.03,108.59 E16-107.1
N$246
  Bottom 0.381: E23.12 196.85,111.76 200.03,111.76 E16-108.1
N$247
  Bottom 0.381: E23.13 196.85,114.3 197.49,114.94 200.03,114.94 E16-109.1
N$248
  Bottom 0.381: E23.14 196.85,116.84 198.75,118.75 200.03,118.75 E16-110.1
N$249
  Bottom 0.381: E23.15 196.85,119.38 200.03,122.56 E16-111.1
N$250
  Bottom 0.381: E23.16 196.22,122.56 200.03,126.37 E16-112.1
N$251
  Bottom 0.381: C23.1 187.32,96.52 183.51,96.52 E16-113.1
N$252
  Bottom 0.381: C23.2 196.22,96.52 200.03,96.52 E16-114.1
N$253
  Bottom 0.381: E26.1 161.93,160.66 158.12,164.47 E16-115.1
N$254
  Bottom 0.381: E26.2 161.29,157.48 158.12,160.66 E16-116.1
N$255
  Bottom 0.381: E26.3 161.29,154.94 159.38,156.85 158.12,156.85 E16-117.1
N$256
  Bottom 0.381: E26.4 161.29,152.4 160.66,153.04 158.12,153.04 E16-118.1
N$257
  Bottom 0.381: E26.5 161.29,149.86 158.12,149.86 E16-119.1
N$258
  Bottom 0.381: E26.6 161.29,147.32 160.66,146.69 158.12,146.69 E16-120.1
N$259
  Bottom 0.381: E26.7 161.29,144.78 159.38,142.88 158.12,142.88 E16-121.1
N$260
  Bottom 0.381: E26.8 161.29,142.24 158.12,139.07 E16-122.1
N$261
  Bottom 0.381: E26.9 171.45,142.24 174.62,139.07 E16-123.1
N$262
  Bottom 0.381: E26.10 171.45,144.78 173.35,142.88 174.62,142.88 E16-124.1
N$263
  Bottom 0.381: E26.11 171.45,147.32 172.09,146.69 174.62,146.69 E16-125.1
N$264
  Bottom 0.381: E26.12 171.45,149.86 174.62,149.86 E16-126.1
N$265
  Bottom 0.381: E26.13 171.45,152.4 172.09,153.04 174.62,153.04 E16-127.1
N$266
  Bottom 0.381: E26.14 171.45,154.94 173.35,156.85 174.62,156.85 E16-128.1
N$267
  Bottom 0.381: E26.15 171.45,157.48 174.62,160.66 E16-129.1
N$268
  Bottom 0.381: E26.16 170.81,160.66 174.62,164.47 E16-130.1
N$269
  Bottom 0.381: C25.1 161.93,96.52 158.12,96.52 E16-131.1
N$270
  Bottom 0.381: C25.2 170.81,96.52 174.62,96.52 E16-132.1
N$271
  Bottom 0.381: E25.1 161.93,122.56 158.12,126.37 E16-133.1
N$272
  Bottom 0.381: E25.2 161.29,119.38 158.12,122.56 E16-134.1
N$273
  Bottom 0.381: E25.3 161.29,116.84 159.38,118.75 158.12,118.75 E16-135.1
N$274
  Bottom 0.381: E25.4 161.29,114.3 160.66,114.94 158.12,114.94 E16-136.1
N$275
  Bottom 0.381: E25.5 161.29,111.76 158.12,111.76 E16-137.1
N$276
  Bottom 0.381: E25.6 161.29,109.22 160.66,108.59 158.12,108.59 E16-138.1
N$277
  Bottom 0.381: E25.7 161.29,106.68 159.38,104.78 158.12,104.78 E16-139.1
N$278
  Bottom 0.381: E25.8 161.29,104.14 158.12,100.97 E16-140.1
N$279
  Bottom 0.381: E25.9 171.45,104.14 174.62,100.97 E16-141.1
N$280
  Bottom 0.381: E25.10 171.45,106.68 173.35,104.78 174.62,104.78 E16-142.1
N$281
  Bottom 0.381: E25.11 171.45,109.22 172.09,108.59 174.62,108.59 E16-143.1
N$282
  Bottom 0.381: E25.12 171.45,111.76 174.62,111.76 E16-144.1
N$283
  Bottom 0.381: E25.13 171.45,114.3 172.09,114.94 174.62,114.94 E16-145.1
N$284
  Bottom 0.381: E25.14 171.45,116.84 173.35,118.75 174.62,118.75 E16-146.1
N$285
  Bottom 0.381: E25.15 171.45,119.38 174.62,122.56 E16-147.1
N$286
  Bottom 0.381: E25.16 170.81,122.56 174.62,126.37 E16-148.1
N$287
  Bottom 0.381: C26.1 161.93,134.62 158.12,134.62 E16-149.1
N$288
  Bottom 0.381: C26.2 170.81,134.62 174.62,134.62 E16-150.1
N$289
  Bottom 0.381: E28.1 136.53,160.66 132.72,164.47 E16-151.1
N$290
  Bottom 0.381: E28.2 135.89,157.48 132.72,160.66 E16-152.1
N$291
  Bottom 0.381: E28.3 135.89,154.94 133.99,156.85 132.72,156.85 E16-153.1
N$292
  Bottom 0.381: E28.4 135.89,152.4 135.25,153.04 132.72,153.04 E16-154.1
N$293
  Bottom 0.381: E28.5 135.89,149.86 132.72,149.86 E16-155.1
N$294
  Bottom 0.381: E28.6 135.89,147.32 135.25,146.69 132.72,146.69 E16-156.1
N$295
  Bottom 0.381: E28.7 135.89,144.78 133.99,142.88 132.72,142.88 E16-157.1
N$296
  Bottom 0.381: E28.8 135.89,142.24 132.72,139.07 E16-158.1
N$297
  Bottom 0.381: E28.9 146.05,142.24 149.22,139.07 E16-159.1
N$298
  Bottom 0.381: E28.10 146.05,144.78 147.96,142.88 149.22,142.88 E16-160.1
N$299
  Bottom 0.381: E28.11 146.05,147.32 146.69,146.69 149.22,146.69 E16-161.1
N$300
  Bottom 0.381: E28.12 146.05,149.86 149.22,149.86 E16-162.1
N$301
  Bottom 0.381: E28.13 146.05,152.4 146.69,153.04 149.22,153.04 E16-163.1
N$302
  Bottom 0.381: E28.14 146.05,154.94 147.96,156.85 149.22,156.85 E16-164.1
N$303
  Bottom 0.381: E28.15 146.05,157.48 149.22,160.66 E16-165.1
N$304
  Bottom 0.381: E28.16 145.41,160.66 149.22,164.47 E16-166.1
N$305
  Bottom 0.381: C27.1 136.53,96.52 132.72,96.52 E16-167.1
N$306
  Bottom 0.381: C27.2 145.41,96.52 149.22,96.52 E16-168.1
N$307
  Top 0.381: E27.1 136.53,122.56 132.72,126.37 E16-169.1
N$308
  Bottom 0.381: E27.2 135.89,119.38 132.72,122.56 E16-170.1
N$309
  Bottom 0.381: E27.3 135.89,116.84 133.99,118.75 132.72,118.75 E16-171.1
N$310
  Bottom 0.381: E27.4 135.89,114.3 135.25,114.94 132.72,114.94 E16-172.1
N$311
  Bottom 0.381: E27.5 135.89,111.76 132.72,111.76 E16-173.1
N$312
  Bottom 0.381: E27.6 135.89,109.22 135.25,108.59 132.72,108.59 E16-174.1
N$313
  Bottom 0.381: E27.7 135.89,106.68 133.99,104.78 132.72,104.78 E16-175.1
N$314
  Bottom 0.381: E27.8 135.89,104.14 132.72,100.97 E16-176.1
N$315
  Bottom 0.381: E27.9 146.05,104.14 149.22,100.97 E16-177.1
N$316
  Bottom 0.381: E27.10 146.05,106.68 147.96,104.78 149.22,104.78 E16-178.1
N$317
  Bottom 0.381: E27.11 146.05,109.22 146.69,108.59 149.22,108.59 E16-179.1
N$318
  Bottom 0.381: E27.12 146.05,111.76 149.22,111.76 E16-180.1
N$319
  Bottom 0.381: E27.13 146.05,114.3 146.69,114.94 149.22,114.94 E16-181.1
N$320
  Bottom 0.381: E27.14 146.05,116.84 147.96,118.75 149.22,118.75 E16-182.1
N$321
  Bottom 0.381: E27.15 146.05,119.38 149.22,122.56 E16-183.1
N$322
  Top 0.381: E27.16 145.41,122.56 149.22,126.37 E16-184.1
N$323
  Bottom 0.381: C28.1 136.53,134.62 132.72,134.62 E16-185.1
N$324
  Bottom 0.381: C28.2 145.41,134.62 149.22,134.62 E16-186.1
N$325
  Bottom 0.381: E30.1 111.12,160.66 107.31,164.47 E16-187.1
N$326
  Bottom 0.381: E30.2 110.49,157.48 107.31,160.66 E16-188.1
N$327
  Bottom 0.381: E30.3 110.49,154.94 108.58,156.85 107.31,156.85 E16-189.1
N$328
  Bottom 0.381: E30.4 110.49,152.4 109.86,153.04 107.31,153.04 E16-190.1
N$329
  Bottom 0.381: E30.5 110.49,149.86 107.31,149.86 E16-191.1
N$330
  Bottom 0.381: E30.6 110.49,147.32 109.86,146.69 107.31,146.69 E16-192.1
N$331
  Bottom 0.381: E30.7 110.49,144.78 108.58,142.88 107.31,142.88 E16-193.1
N$332
  Bottom 0.381: E30.8 110.49,142.24 107.31,139.07 E16-194.1
N$333
  Bottom 0.381: E30.9 120.65,142.24 123.83,139.07 E16-195.1
N$334
  Bottom 0.381: E30.10 120.65,144.78 122.56,142.88 123.83,142.88 E16-196.1
N$335
  Bottom 0.381: E30.11 120.65,147.32 121.28,146.69 123.83,146.69 E16-197.1
N$336
  Bottom 0.381: E30.12 120.65,149.86 123.83,149.86 E16-198.1
N$337
  Bottom 0.381: E30.13 120.65,152.4 121.28,153.04 123.83,153.04 E16-199.1
N$338
  Bottom 0.381: E30.14 120.65,154.94 122.56,156.85 123.83,156.85 E16-200.1
N$339
  Bottom 0.381: E30.15 120.65,157.48 123.83,160.66 E16-201.1
N$340
  Bottom 0.381: E30.16 120.02,160.66 123.83,164.47 E16-202.1
N$341
  Bottom 0.381: C29.1 111.12,96.52 107.31,96.52 E16-203.1
N$342
  Bottom 0.381: C29.2 120.02,96.52 123.83,96.52 E16-204.1
N$343
  Top 0.381: E29.1 111.12,122.56 107.31,126.37 E16-205.1
N$344
  Bottom 0.381: E29.2 110.49,119.38 107.31,122.56 E16-206.1
N$345
  Bottom 0.381: E29.3 110.49,116.84 108.58,118.75 107.31,118.75 E16-207.1
N$346
  Bottom 0.381: E29.4 110.49,114.3 109.86,114.94 107.31,114.94 E16-208.1
N$347
  Bottom 0.381: E29.5 110.49,111.76 107.31,111.76 E16-209.1
N$348
  Bottom 0.381: E29.6 110.49,109.22 109.86,108.59 107.31,108.59 E16-210.1
N$349
  Bottom 0.381: E29.7 110.49,106.68 108.58,104.78 107.31,104.78 E16-211.1
N$350
  Bottom 0.381: E29.8 110.49,104.14 107.31,100.97 E16-212.1
N$351
  Bottom 0.381: E29.9 120.65,104.14 123.83,100.97 E16-213.1
N$352
  Bottom 0.381: E29.10 120.65,106.68 122.56,104.78 123.83,104.78 E16-214.1
N$353
  Bottom 0.381: E29.11 120.65,109.22 121.28,108.59 123.83,108.59 E16-215.1
N$354
  Bottom 0.381: E29.12 120.65,111.76 123.83,111.76 E16-216.1
N$355
  Bottom 0.381: E29.13 120.65,114.3 121.28,114.94 123.83,114.94 E16-217.1
N$356
  Bottom 0.381: E29.14 120.65,116.84 122.56,118.75 123.83,118.75 E16-218.1
N$357
  Bottom 0.381: E29.15 120.65,119.38 123.83,122.56 E16-219.1
N$358
  Top 0.381: E29.16 120.02,122.56 123.83,126.37 E16-220.1
N$359
  Bottom 0.381: C32.1 85.72,134.62 81.92,134.62 E16-221.1
N$360
  Bottom 0.381: C32.2 94.61,134.62 98.42,134.62 E16-222.1
N$361
  Bottom 0.381: E32.1 85.72,160.66 81.92,164.47 E16-223.1
N$362
  Bottom 0.381: E32.2 85.09,157.48 81.92,160.66 E16-224.1
N$363
  Bottom 0.381: E32.3 85.09,154.94 83.19,156.85 81.92,156.85 E16-225.1
N$364
  Bottom 0.381: E32.4 85.09,152.4 84.45,153.04 81.92,153.04 E16-226.1
N$365
  Bottom 0.381: E32.5 85.09,149.86 81.92,149.86 E16-227.1
N$366
  Bottom 0.381: E32.6 85.09,147.32 84.45,146.69 81.92,146.69 E16-228.1
N$367
  Bottom 0.381: E32.7 85.09,144.78 83.19,142.88 81.92,142.88 E16-229.1
N$368
  Bottom 0.381: E32.8 85.09,142.24 81.92,139.07 E16-230.1
N$369
  Bottom 0.381: E32.9 95.25,142.24 98.42,139.07 E16-231.1
N$370
  Bottom 0.381: E32.10 95.25,144.78 97.16,142.88 98.42,142.88 E16-232.1
N$371
  Bottom 0.381: E32.11 95.25,147.32 95.89,146.69 98.42,146.69 E16-233.1
N$372
  Bottom 0.381: E32.12 95.25,149.86 98.42,149.86 E16-234.1
N$373
  Bottom 0.381: E32.13 95.25,152.4 95.89,153.04 98.42,153.04 E16-235.1
N$374
  Bottom 0.381: E32.14 95.25,154.94 97.16,156.85 98.42,156.85 E16-236.1
N$375
  Bottom 0.381: E32.15 95.25,157.48 98.42,160.66 E16-237.1
N$376
  Bottom 0.381: E32.16 94.61,160.66 98.42,164.47 E16-238.1
N$377
  Bottom 0.381: C31.1 85.72,96.52 81.92,96.52 E16-239.1
N$378
  Bottom 0.381: C31.2 94.61,96.52 98.42,96.52 E16-240.1
N$379
  Top 0.381: E31.1 85.72,122.56 81.92,126.37 E16-241.1
N$380
  Bottom 0.381: E31.2 85.09,119.38 81.92,122.56 E16-242.1
N$381
  Bottom 0.381: E31.3 85.09,116.84 83.19,118.75 81.92,118.75 E16-243.1
N$382
  Bottom 0.381: E31.4 85.09,114.3 84.45,114.94 81.92,114.94 E16-244.1
N$383
  Bottom 0.381: E31.5 85.09,111.76 81.92,111.76 E16-245.1
N$384
  Bottom 0.381: E31.6 85.09,109.22 84.45,108.59 81.92,108.59 E16-246.1
N$385
  Bottom 0.381: E31.7 85.09,106.68 83.19,104.78 81.92,104.78 E16-247.1
N$386
  Bottom 0.381: E31.8 85.09,104.14 81.92,100.97 E16-248.1
N$387
  Bottom 0.381: E31.9 95.25,104.14 98.42,100.97 E16-249.1
N$388
  Bottom 0.381: E31.10 95.25,106.68 97.16,104.78 98.42,104.78 E16-250.1
N$389
  Bottom 0.381: E31.11 95.25,109.22 95.89,108.59 98.42,108.59 E16-251.1
N$390
  Bottom 0.381: E31.12 95.25,111.76 98.42,111.76 E16-252.1
N$391
  Bottom 0.381: E31.13 95.25,114.3 95.89,114.94 98.42,114.94 E16-253.1
N$392
  Bottom 0.381: E31.14 95.25,116.84 97.16,118.75 98.42,118.75 E16-254.1
N$393
  Bottom 0.381: E31.15 95.25,119.38 98.42,122.56 E16-255.1
N$394
  Top 0.381: E31.16 94.61,122.56 98.42,126.37 E16-256.1
N$395
  Bottom 0.381: C34.1 60.33,134.62 56.52,134.62 E16-257.1
N$396
  Bottom 0.381: C34.2 69.22,134.62 73.03,134.62 E16-258.1
N$397
  Bottom 0.381: E34.1 60.33,160.66 56.52,164.47 E16-259.1
N$398
  Bottom 0.381: E34.2 59.69,157.48 56.52,160.66 E16-260.1
N$399
  Bottom 0.381: E34.3 59.69,154.94 57.78,156.85 56.52,156.85 E16-261.1
N$400
  Bottom 0.381: E34.4 59.69,152.4 59.05,153.04 56.52,153.04 E16-262.1
N$401
  Bottom 0.381: E34.5 59.69,149.86 56.52,149.86 E16-263.1
N$402
  Bottom 0.381: E34.6 59.69,147.32 59.05,146.69 56.52,146.69 E16-264.1
N$403
  Bottom 0.381: E34.7 59.69,144.78 57.78,142.88 56.52,142.88 E16-265.1
N$404
  Bottom 0.381: E34.8 59.69,142.24 56.52,139.07 E16-266.1
N$405
  Bottom 0.381: E34.9 69.85,142.24 73.03,139.07 E16-267.1
N$406
  Bottom 0.381: E34.10 69.85,144.78 71.75,142.88 73.03,142.88 E16-268.1
N$407
  Bottom 0.381: E34.11 69.85,147.32 70.48,146.69 73.03,146.69 E16-269.1
N$408
  Bottom 0.381: E34.12 69.85,149.86 73.03,149.86 E16-270.1
N$409
  Bottom 0.381: E34.13 69.85,152.4 70.48,153.04 73.03,153.04 E16-271.1
N$410
  Bottom 0.381: E34.14 69.85,154.94 71.75,156.85 73.03,156.85 E16-272.1
N$411
  Bottom 0.381: E34.15 69.85,157.48 73.03,160.66 E16-273.1
N$412
  Bottom 0.381: E34.16 69.22,160.66 73.03,164.47 E16-274.1
N$413
  Bottom 0.381: C30.1 111.12,134.62 107.31,134.62 E16-275.1
N$414
  Bottom 0.381: C30.2 120.02,134.62 123.83,134.62 E16-276.1
N$415
  Bottom 0.381: E33.1 60.33,122.56 56.52,126.37 E16-277.1
N$416
  Bottom 0.381: E33.2 59.69,119.38 56.52,122.56 E16-278.1
N$417
  Bottom 0.381: E33.3 59.69,116.84 57.78,118.75 56.52,118.75 E16-279.1
N$418
  Bottom 0.381: E33.4 59.69,114.3 59.05,114.94 56.52,114.94 E16-280.1
N$419
  Bottom 0.381: E33.5 59.69,111.76 56.52,111.76 E16-281.1
N$420
  Bottom 0.381: E33.6 59.69,109.22 59.05,108.59 56.52,108.59 E16-282.1
N$421
  Bottom 0.381: E33.7 59.69,106.68 57.78,104.78 56.52,104.78 E16-283.1
N$422
  Bottom 0.381: E33.8 59.69,104.14 56.52,100.97 E16-284.1
N$423
  Bottom 0.381: E33.9 69.85,104.14 73.03,100.97 E16-285.1
N$424
  Bottom 0.381: E33.10 69.85,106.68 71.75,104.78 73.03,104.78 E16-286.1
N$425
  Bottom 0.381: E33.11 69.85,109.22 70.48,108.59 73.03,108.59 E16-287.1
N$426
  Bottom 0.381: E33.12 69.85,111.76 73.03,111.76 E16-288.1
N$427
  Bottom 0.381: E33.13 69.85,114.3 70.48,114.94 73.03,114.94 E16-289.1
N$428
  Bottom 0.381: E33.14 69.85,116.84 71.75,118.75 73.03,118.75 E16-290.1
N$429
  Bottom 0.381: E33.15 69.85,119.38 73.03,122.56 E16-291.1
N$430
  Bottom 0.381: E33.16 69.22,122.56 69.22,126.37 73.03,126.37 E16-292.1
N$431
  Bottom 0.381: C33.1 60.33,96.52 56.52,96.52 E16-293.1
N$432
  Bottom 0.381: C33.2 69.22,96.52 73.03,96.52 E16-294.1
N$433
  Bottom 0.381: E35.1 34.92,122.56 31.11,126.37 E16-295.1
N$434
  Bottom 0.381: E35.2 34.29,119.38 31.11,122.56 E16-296.1
N$435
  Bottom 0.381: E35.3 34.29,116.84 32.38,118.75 31.11,118.75 E16-297.1
N$436
  Bottom 0.381: E35.4 34.29,114.3 33.66,114.94 31.11,114.94 E16-298.1
N$437
  Bottom 0.381: E35.5 34.29,111.76 31.11,111.76 E16-299.1
N$438
  Bottom 0.381: E35.6 34.29,109.22 33.66,108.59 31.11,108.59 E16-300.1
N$439
  Bottom 0.381: E35.7 34.29,106.68 32.38,104.78 31.11,104.78 E16-301.1
N$440
  Bottom 0.381: E35.8 34.29,104.14 31.11,100.97 E16-302.1
N$441
  Bottom 0.381: E35.9 44.45,104.14 47.62,100.97 E16-303.1
N$442
  Bottom 0.381: E35.10 44.45,106.68 46.35,104.78 47.62,104.78 E16-304.1
N$443
  Bottom 0.381: E35.11 44.45,109.22 45.09,108.59 47.62,108.59 E16-305.1
N$444
  Bottom 0.381: E35.12 44.45,111.76 47.62,111.76 E16-306.1
N$445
